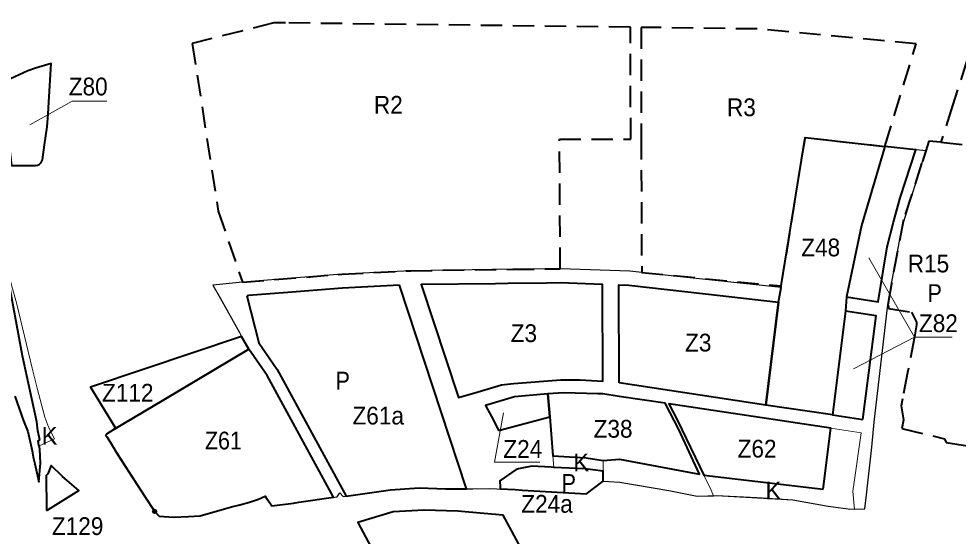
# Model space of a CAD drawing. Extents: x -650276 to -642489, y -1074311 to -1066658.
# Drawn here: x -647871 to -646603, y -1069891 to -1069193 of the extents above; entities that cross this region are included whole.
import ezdxf

# ---------------------------------------------------------------- set-up
doc = ezdxf.new("R2010")
doc.units = 0
doc.header["$LTSCALE"] = 9.6
doc.header["$PDMODE"] = 32
doc.header["$PDSIZE"] = 4.8
doc.linetypes.add('MEDIUM_DASHED', pattern=[4.5, 3, -1.5])
for name, color, linetype, lineweight in [('42', 7, 'Continuous', 25), ('44', 7, 'Continuous', 40), ('45', 7, 'Continuous', 40), ('46', 7, 'Continuous', 13), ('47', 7, 'Continuous', 13), ('48', 7, 'Continuous', 13), ('60', 7, 'Continuous', 35), ('61', 7, 'MEDIUM_DASHED', 40), ('62', 7, 'Continuous', 35)]:
    doc.layers.add(name, color=color, linetype=linetype, lineweight=lineweight)

msp = doc.modelspace()

# ---------------------------------------------------------------- linework, layer by layer
at = {"layer": '42'}
for points in [[(-647235.49, -1069826.51), (-647205.603, -1069827.72), (-647191.66, -1069828.58), (-647201.106, -1069827.997), (-647191.66, -1069828.58), (-647104.741, -1069833.568), (-647082.145, -1069816.321), (-647074.72, -1069816.8), (-647060.029, -1069817.854), (-646993.81, -1069829.12), (-646993.81, -1069829.12), (-646955.45, -1069836.93), (-646940.94, -1069836.34), (-646933.39, -1069836.51), (-646929.67, -1069835.68), (-646826.63, -1069841.84), (-646778.74, -1069850.44), (-646751.8, -1069853.72), (-646743.31, -1069854.26), (-646729.54, -1069853.69), (-646727.09, -1069835.05), (-646719.79, -1069770.87), (-646716.98, -1069736.73), (-646698.96, -1069582.26), (-646698.96, -1069582.26), (-646698.4, -1069578.93), (-646693.58, -1069550.28), (-646679.13, -1069473.51), (-646647.141, -1069370.826), (-646702.425, -1069364.771), (-646809.879, -1069353.002), (-646842.103, -1069553.182), (-646842.441, -1069555.283), (-646910.029, -1069548.006), (-646986.633, -1069539.757), (-647046.325, -1069533.275), (-647140.008, -1069530.068), (-647204.293, -1069530.647), (-647341.697, -1069532.602), (-647434.969, -1069537.141), (-647523.931, -1069544.499), (-647568.792, -1069548.21), (-647608.81, -1069551.868), (-647598.735, -1069570.026), (-647573.15, -1069616.16), (-647570.37, -1069621.18), (-647570.37, -1069621.18), (-647701.61, -1069665.279), (-647774.11, -1069689.64), (-647740.74, -1069744.24), (-647742.36, -1069746.93), (-647752.32, -1069752.95), (-647753.7, -1069753.9), (-647745.84, -1069766.71), (-647687.45, -1069857.15), (-647681.51, -1069863.72), (-647661.79, -1069864.92), (-647641.78, -1069864.26), (-647625.83, -1069863.19), (-647593.07, -1069853.74), (-647572.63, -1069848.63), (-647559.47, -1069844.92), (-647547.12, -1069840.87), (-647538.34, -1069836.68), (-647531.33, -1069847.23), (-647529.5, -1069849.99), (-647492.76, -1069845.02), (-647441.19, -1069837.6), (-647437.46, -1069832.27), (-647433.32, -1069837.33), (-647369.3, -1069828.22), (-647330.46, -1069825.51), (-647294.38, -1069826.88)], [(-647294.38, -1069826.88), (-647270.09, -1069827.02), (-647258.143, -1069827.094), (-647235.49, -1069826.51)]]:
    msp.add_lwpolyline(points, dxfattribs=at)
at = {"layer": '44'}
msp.add_line((-646772.907, -1069727.177), (-646732.143, -1069733.308), dxfattribs=at)
for points in [[(-647860.52, -1069390.72), (-647848.24, -1069390.65), (-647845.25, -1069390.07), (-647843.41, -1069389.23), (-647841.81, -1069387.99), (-647840.42, -1069386.51), (-647839.4, -1069384.73), (-647838.79, -1069382.86), (-647836.2, -1069362.68), (-647832.29, -1069338.58), (-647832.29, -1069338.58), (-647831.19, -1069320.69), (-647830.23, -1069305.38), (-647826.928, -1069253.199), (-647848.17, -1069259.21), (-647858.37, -1069263.03), (-647893.553, -1069279.017), (-647880.326, -1069390.832)], [(-646660.526, -1069369.36), (-646702.425, -1069364.771), (-646733.74, -1069471.688), (-646754.066, -1069567.993), (-646711.442, -1069574.759), (-646704.68, -1069533.06), (-646699.07, -1069500.57), (-646690.51, -1069466.97), (-646681.5, -1069434.17)]]:
    msp.add_lwpolyline(points, close=True, dxfattribs=at)
at = {"layer": '44', "lineweight": 13}
for points in [[(-647751.811, -1069303.761), (-647798.61, -1069303.761), (-647856.005, -1069335.572)], [(-647751.811, -1069303.761), (-647798.61, -1069303.761), (-647856.005, -1069335.572)], [(-646611.673, -1069622.045), (-646662.372, -1069622.045), (-646744.747, -1069664.938), (-646662.372, -1069622.045), (-646723.996, -1069515.165)]]:
    msp.add_lwpolyline(points, dxfattribs=at)
at = {"layer": '44'}
for points in [[(-647865.69, -1069647.32), (-647887.649, -1069528.021), (-647887.087, -1069527.229)], [(-646725.82, -1069684.5), (-646714.037, -1069593.585), (-646755.269, -1069587.04), (-646772.907, -1069727.177)], [(-647842.438, -1069760.647), (-647845.086, -1069748.753), (-647846.484, -1069736.663), (-647855.158, -1069695.232), (-647865.69, -1069647.32)], [(-646732.143, -1069733.308), (-646725.82, -1069684.5), (-646725.82, -1069684.5)], [(-647875.82, -1069701.85), (-647864.19, -1069735.12), (-647858.44, -1069749.43), (-647852.63, -1069775.7), (-647850.66, -1069785.74), (-647849.165, -1069793.367), (-647843.74, -1069817.63), (-647841.402, -1069792.351)], [(-647841.402, -1069792.351), (-647842.489, -1069773.282), (-647842.622, -1069770.956), (-647843.337, -1069769.013), (-647843.443, -1069768.293), (-647843.458, -1069768.256), (-647843.449, -1069768.252), (-647844.371, -1069761.991), (-647842.438, -1069760.647)]]:
    msp.add_lwpolyline(points, dxfattribs=at)
at = {"layer": '45'}
for points in [[(-646842.441, -1069555.283), (-646842.103, -1069553.182), (-646809.879, -1069353.002), (-646702.425, -1069364.771), (-646702.425, -1069364.771), (-646702.425, -1069364.771), (-646702.425, -1069364.771), (-646702.425, -1069364.771), (-646733.74, -1069471.688), (-646733.74, -1069471.688), (-646754.066, -1069567.993)], [(-646842.441, -1069555.283), (-646842.103, -1069553.182), (-646809.879, -1069353.002), (-646702.425, -1069364.771), (-646702.425, -1069364.771), (-646702.425, -1069364.771), (-646702.425, -1069364.771), (-646702.425, -1069364.771), (-646733.74, -1069471.688), (-646733.74, -1069471.688), (-646754.066, -1069567.993)], [(-647356.899, -1069552.034), (-647433.779, -1069556.106), (-647433.779, -1069556.106), (-647513.66, -1069562.249), (-647514.067, -1069562.282), (-647560.836, -1069566.036), (-647563.104, -1069566.28)], [(-647369.3, -1069828.22), (-647330.46, -1069825.51), (-647294.38, -1069826.88), (-647270.09, -1069827.02), (-647266.581, -1069827.042), (-647356.899, -1069552.034)], [(-647563.104, -1069566.28), (-647546.777, -1069629.901), (-647521.943, -1069665.763)], [(-646754.066, -1069567.993), (-646755.269, -1069587.04), (-646772.906, -1069727.176), (-646863, -1069714), (-646846, -1069575), (-646842.441, -1069555.283)], [(-646754.066, -1069567.993), (-646755.269, -1069587.04), (-646772.906, -1069727.176), (-646863, -1069714), (-646846, -1069575), (-646842.441, -1069555.283)], [(-647570.37, -1069621.18), (-647701.61, -1069665.279), (-647774.11, -1069689.64), (-647740.74, -1069744.24), (-647742.36, -1069746.93), (-647674.901, -1069706.701)], [(-647570.37, -1069621.18), (-647701.61, -1069665.279), (-647774.11, -1069689.64), (-647740.74, -1069744.24), (-647742.36, -1069746.93), (-647674.901, -1069706.701)], [(-647674.901, -1069706.701), (-647560.36, -1069638.39), (-647570.37, -1069621.18)], [(-647674.901, -1069706.701), (-647560.36, -1069638.39), (-647570.37, -1069621.18)], [(-647560.36, -1069638.39), (-647674.901, -1069706.701), (-647742.36, -1069746.93)], [(-647446.322, -1069838.338), (-647535.588, -1069674.163), (-647560.36, -1069638.39)], [(-647521.943, -1069665.763), (-647428.993, -1069836.714), (-647369.3, -1069828.22)], [(-647742.36, -1069746.93), (-647752.32, -1069752.95), (-647753.7, -1069753.9)], [(-647753.7, -1069753.9), (-647751.66, -1069757.12), (-647745.84, -1069766.71), (-647737.17, -1069780.85), (-647700.58, -1069837.2), (-647687.45, -1069857.15), (-647681.51, -1069863.72)], [(-647641.78, -1069864.26), (-647625.83, -1069863.19), (-647593.07, -1069853.74), (-647583.62, -1069851.13), (-647572.63, -1069848.63), (-647559.47, -1069844.92), (-647547.12, -1069840.87), (-647538.34, -1069836.68), (-647536.82, -1069838.87), (-647531.33, -1069847.23), (-647529.5, -1069849.99), (-647500.03, -1069846.28), (-647492.76, -1069845.02), (-647446.322, -1069838.338)], [(-647681.51, -1069863.72), (-647661.79, -1069864.92), (-647641.78, -1069864.26)]]:
    msp.add_lwpolyline(points, dxfattribs=at)
for points in [[(-647251.002, -1069695.852), (-647219.628, -1069686.746), (-647203.374, -1069684.716), (-647139.649, -1069679.961), (-647113.255, -1069679.966), (-647082.761, -1069681.399), (-647083.356, -1069551.018), (-647140.247, -1069549.071), (-647158.572, -1069549.252), (-647211.05, -1069549.77), (-647227.623, -1069550.23), (-647327.682, -1069551.263), (-647277.71, -1069703.421)], [(-647251.002, -1069695.852), (-647219.628, -1069686.746), (-647203.374, -1069684.716), (-647139.649, -1069679.961), (-647113.255, -1069679.966), (-647082.761, -1069681.399), (-647083.356, -1069551.018), (-647140.247, -1069549.071), (-647158.572, -1069549.252), (-647211.05, -1069549.77), (-647227.623, -1069550.23), (-647327.682, -1069551.263), (-647277.71, -1069703.421)], [(-647060.7, -1069683.894), (-647061.304, -1069551.773), (-647047.648, -1069552.245), (-646944.168, -1069563.743), (-646846, -1069575), (-646863, -1069714)], [(-647060.7, -1069683.894), (-647061.304, -1069551.773), (-647047.648, -1069552.245), (-646944.168, -1069563.743), (-646846, -1069575), (-646863, -1069714)], [(-647223.66, -1069748.26), (-647154.33, -1069729.69), (-647156.782, -1069698.901), (-647202.181, -1069702.678), (-647240.994, -1069714.513), (-647230.16, -1069734.42)], [(-647223.66, -1069748.26), (-647154.33, -1069729.69), (-647156.782, -1069698.901), (-647202.181, -1069702.678), (-647240.994, -1069714.513), (-647230.16, -1069734.42)], [(-647060.617, -1069702.116), (-647082.682, -1069698.791), (-647089.456, -1069698.579), (-647135.585, -1069697.137), (-647156.782, -1069698.901), (-647154.33, -1069729.69), (-647150.138, -1069782.334), (-647105.334, -1069785.168), (-647082.271, -1069788.81), (-647060.23, -1069786.932), (-646952.56, -1069807.13), (-646980.4, -1069746.98), (-646998.56, -1069711.443)], [(-646785.437, -1069827.534), (-646775.286, -1069745.022), (-646993.771, -1069712.163), (-646981.92, -1069734.86), (-646946.369, -1069808.291)], [(-646785.437, -1069827.534), (-646775.286, -1069745.022), (-646993.771, -1069712.163), (-646981.92, -1069734.86), (-646946.369, -1069808.291)], [(-647833.172, -1069855.944), (-647833.172, -1069855.944), (-647831.62, -1069854.99), (-647789.55, -1069829.12), (-647811.83, -1069810.39), (-647827.16, -1069795.32), (-647831.32, -1069806.56), (-647833.91, -1069808.91), (-647833.2, -1069854.15)], [(-647196.616, -1069800.068), (-647199.65, -1069800.69), (-647221.87, -1069816.21), (-647221.28, -1069824.74), (-647221.14, -1069826.761), (-647201.106, -1069827.997), (-647191.66, -1069828.58), (-647104.741, -1069833.568), (-647082.145, -1069816.321), (-647082.206, -1069802.916), (-647096.39, -1069801.15), (-647107.04, -1069799.84), (-647148.9, -1069797.88), (-647152.39, -1069797.7), (-647178.73, -1069796.4)], [(-647365.866, -1069857.774), (-647413.461, -1069872.442), (-647343.28, -1070003.81), (-647339.69, -1070001.95), (-647330.5, -1069997.19), (-647304.05, -1069983.79), (-647294.257, -1070002.745), (-647242.254, -1069980.33), (-647229.096, -1069974.658), (-647235, -1069963), (-647176.499, -1069938.333), (-647205.781, -1069883.796), (-647217.177, -1069862.57), (-647243.231, -1069860.34), (-647278.525, -1069857.002), (-647323.794, -1069855.468)], [(-647365.866, -1069857.774), (-647413.461, -1069872.442), (-647343.28, -1070003.81), (-647339.69, -1070001.95), (-647330.5, -1069997.19), (-647304.05, -1069983.79), (-647294.257, -1070002.745), (-647242.254, -1069980.33), (-647229.096, -1069974.658), (-647235, -1069963), (-647176.499, -1069938.333), (-647205.781, -1069883.796), (-647217.177, -1069862.57), (-647243.231, -1069860.34), (-647278.525, -1069857.002), (-647323.794, -1069855.468)]]:
    msp.add_lwpolyline(points, close=True, dxfattribs=at)
msp.add_point((-647687.45, -1069857.15), dxfattribs=at)
at = {"layer": '46'}
msp.add_lwpolyline([(-647167.693, -1069791.112), (-647229.126, -1069791.112), (-647217.012, -1069724.439)], dxfattribs=at)
msp.add_lwpolyline([(-647167.693, -1069791.112), (-647229.126, -1069791.112), (-647217.012, -1069724.439)], dxfattribs=at)
at = {"layer": '47'}
for p, q in [((-647150.141, -1069782.334), (-647148.9, -1069797.88)), ((-647107.04, -1069799.84), (-647096.39, -1069801.15))]:
    msp.add_line(p, q, dxfattribs=at)
msp.add_lwpolyline([(-647845.086, -1069748.753), (-647842.438, -1069760.647), (-647844.371, -1069761.991), (-647843.337, -1069769.013), (-647822.54, -1069759.29), (-647830, -1069744.7), (-647835.76, -1069730.01), (-647845.85, -1069691.2), (-647852.44, -1069664.03), (-647873.43, -1069577.87), (-647887.087, -1069527.229), (-647865.69, -1069647.32), (-647855.158, -1069695.232), (-647846.484, -1069736.663)], close=True, dxfattribs=at)
for points in [[(-646778.74, -1069850.44), (-646751.8, -1069853.72), (-646743.31, -1069854.26), (-646743.7, -1069850.07), (-646745.56, -1069829.84), (-646743.85, -1069817.72), (-646734.48, -1069751.35), (-646775.286, -1069745.022), (-646785.437, -1069827.534), (-646946.369, -1069808.291), (-646936.6, -1069828.47), (-646933.39, -1069836.51)], [(-647082.271, -1069788.81), (-647105.334, -1069785.168), (-647105.334, -1069785.168), (-647150.138, -1069782.334)], [(-647096.39, -1069801.15), (-647096.39, -1069801.15), (-647082.206, -1069802.917), (-647082.271, -1069788.81)], [(-647148.9, -1069797.88), (-647148.9, -1069797.88), (-647107.04, -1069799.84)], [(-646933.39, -1069836.51), (-646933.39, -1069836.51), (-646929.67, -1069835.68), (-646875, -1069838.65), (-646853.88, -1069839.8), (-646826.63, -1069841.84), (-646778.74, -1069850.44), (-646778.74, -1069850.44)]]:
    msp.add_lwpolyline(points, dxfattribs=at)
at = {"layer": '61'}
msp.add_line((-646626.774, -1069359.349), (-646642.89, -1069357.68), dxfattribs=at)
for points in [[(-646572.586, -1069194.485), (-646577.878, -1069206.485), (-646611.107, -1069309.68), (-646626.774, -1069359.349), (-646580.797, -1069364.111), (-646571.479, -1069363.822), (-646526.31, -1069184.381), (-646570.296, -1069190.776)], [(-647045.7, -1069204.106), (-647511.107, -1069198.223), (-647526.615, -1069198.093), (-647636.743, -1069226.014), (-647601.568, -1069452.14), (-647568.792, -1069548.21), (-647434.969, -1069537.141), (-647341.697, -1069532.602), (-647204.293, -1069530.647), (-647140.334, -1069530.057), (-647141.134, -1069354.872), (-647045.123, -1069355.003)], [(-647031.152, -1069204.288), (-647031.152, -1069353.712), (-647030.324, -1069535.053), (-646842.103, -1069553.182), (-646809.879, -1069353.002), (-646702.425, -1069364.771), (-646659.946, -1069226.375), (-646874.542, -1069206.4)]]:
    msp.add_lwpolyline(points, close=True, dxfattribs=at)
msp.add_lwpolyline([(-646642.89, -1069357.68), (-646652.72, -1069388.08), (-646677.18, -1069463.79), (-646693.58, -1069550.28), (-646698.4, -1069578.93), (-646697.31, -1069579.97), (-646697.31, -1069583.47), (-646666.36, -1069588.57), (-646659.83, -1069601.8), (-646659.52, -1069605.53), (-646662.57, -1069621.66), (-646671.69, -1069669.92), (-646678.52, -1069705.63), (-646680.28, -1069714.83), (-646677.36, -1069733.65), (-646679.46, -1069745.37), (-646622, -1069759.34), (-646619.49, -1069764.46), (-646585.51, -1069769.57), (-646583.457, -1069759.191), (-646548.91, -1069578.56), (-646580.797, -1069364.111)], dxfattribs=at)

# ---------------------------------------------------------------- texts
at = {"layer": '44', "width": 0.95}
for s, p in [('Z80', (-647803.311, -1069296.044)), ('Z80', (-647803.311, -1069296.044)), ('Z82', (-646656.364, -1069615.463))]:
    msp.add_text(s, height=24, dxfattribs=at).set_placement(p)
at = {"layer": '46'}
for s, width, p in [('Z48', 0.95, (-646815.179, -1069513.185)), ('Z48', 0.95, (-646815.179, -1069513.185)), ('Z3', 0.95, (-647207.094, -1069628.872)), ('Z3', 0.95, (-647207.094, -1069628.872)), ('Z3', 0.95, (-646971.871, -1069641.589)), ('Z3', 0.95, (-646971.871, -1069641.589)), ('Z112', 0.95, (-647758.383, -1069709.22)), ('Z112', 0.95, (-647758.383, -1069709.22)), ('Z61a', 0.95, (-647420.53, -1069740.066)), ('Z38', 0.95, (-647095.223, -1069757.854)), ('Z38', 0.95, (-647095.223, -1069757.854)), ('Z61', 0.9, (-647619.576, -1069773.738)), ('Z24', 0.95, (-647217.069, -1069785.057)), ('Z24', 0.95, (-647217.069, -1069785.057)), ('Z62', 0.95, (-646900.991, -1069784.684)), ('Z62', 0.95, (-646900.991, -1069784.684)), ('Z24a', 0.95, (-647192.847, -1069859.131)), ('Z129', 0.95, (-647826.051, -1069889.189))]:
    msp.add_text(s, height=24, dxfattribs=dict(at, width=width)).set_placement(p)
at = {"layer": '48'}
for p in [(-647839.874, -1069767.492), (-647122.713, -1069803.226), (-646863.536, -1069841.154)]:
    msp.add_text('K', height=24, dxfattribs=at).set_placement(p)
at = {"layer": '60', "width": 0.9}
for p in [(-646644.717, -1069574.793), (-646644.717, -1069574.793), (-647443.274, -1069692.913), (-647443.274, -1069692.913), (-647138.27, -1069830.996), (-647138.27, -1069830.996)]:
    msp.add_text('P', height=24, dxfattribs=at).set_placement(p)
at = {"layer": '62', "width": 0.95}
for s, p in [('R2', (-647391.654, -1069320.724)), ('R2', (-647391.654, -1069320.724)), ('R3', (-646915.354, -1069324.087)), ('R3', (-646915.354, -1069324.087)), ('R15', (-646671.455, -1069534.875)), ('R15', (-646671.455, -1069534.875))]:
    msp.add_text(s, height=24, dxfattribs=at).set_placement(p)

doc.saveas('drawing.dxf')
